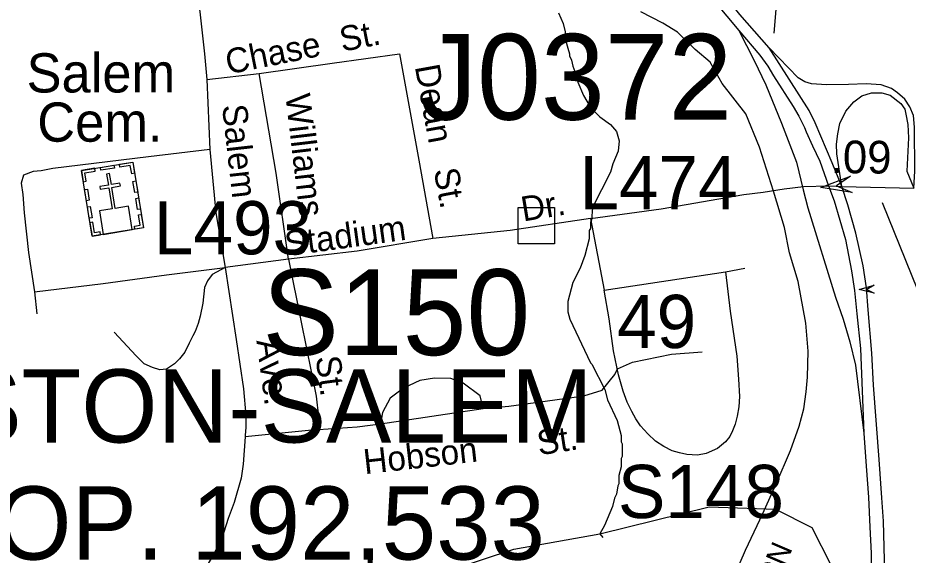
# Model space of a CAD drawing. Extents: x 1553981 to 1780076, y 812965 to 996873.
# Drawn here: x 1633663.3 to 1634089, y 847717.4 to 847974.3 of the extents above; entities that cross this region are included whole.
import ezdxf

# ---------------------------------------------------------------- set-up
doc = ezdxf.new("R2010")
doc.units = 0
for name, color, linetype in [('Exist Aviation Commercial or Municipal CELL', 7, 'Continuous'), ('Exist Aviation Field Marked Auxiliary CELL', 7, 'Continuous'), ('Exist Cultural School High CELL', 7, 'Continuous'), ('Exist Hydrographic Creek Single Shore', 7, 'Continuous'), ('Exist Hydrographic Misc Water Feature', 7, 'Continuous'), ('Exist Railroad Mainline', 7, 'Continuous'), ('Exist Railroad Mainline Label', 7, 'Continuous'), ('Exist Road Non-System Structure Non-Sys Other CELL', 7, 'Continuous'), ('Exist Road Non-System Structure Non-Sys Other Number Label', 7, 'Continuous'), ('Exist Road Non-System Type 51 Label', 7, 'Continuous'), ('Exist Road Primary Interstate Structure Cantilever Sign Number Label', 7, 'Continuous'), ('Exist Road Primary Interstate Structure Ovrhead Sign Number Label', 7, 'Continuous'), ('Exist Road Primary US Divided Attributed', 7, 'Continuous'), ('Exist Road Primary US Ramp 1 Lane  Attributed', 7, 'Continuous'), ('Exist Road Secondary Mileage Hundredths English Label', 7, 'Continuous'), ('Exist Road Secondary Structure Standard Bridge Attributed CELL', 7, 'Continuous'), ('Exist Road Secondary Structure Standard Bridge Number Label', 7, 'Continuous'), ('Exist Road Secondary Type 51 Number Label', 7, 'Continuous'), ('Exist Road Secondary Type 51 Undivided 4 Lane Attributed', 7, 'Continuous'), ('Map Preparation Border Black Inside Shape', 7, 'Continuous'), ('Map Preparation Border County Name Lower Right Label', 7, 'Continuous')]:
    doc.layers.add(name, color=color, linetype=linetype)

msp = doc.modelspace()

# ---------------------------------------------------------------- linework, layer by layer
at = {"layer": 'Exist Aviation Commercial or Municipal CELL'}
for points in [[(1633693.69, 847901.36), (1633718.25, 847905.37), (1633723.38, 847873.96), (1633698.82, 847869.94)], [(1633694.56, 847896.01), (1633695.96, 847896.24), (1633695.31, 847900.21), (1633700.31, 847901.03), (1633700.09, 847902.4), (1633693.69, 847901.36)], [(1633702.82, 847902.85), (1633709.22, 847903.89), (1633709.45, 847902.49), (1633703.05, 847901.44)], [(1633719.13, 847900.02), (1633717.73, 847899.79), (1633717.08, 847903.76), (1633712.08, 847902.95), (1633711.85, 847904.32), (1633718.26, 847905.36)], [(1633704.13, 847870.82), (1633717.97, 847873.08), (1633716.14, 847884.25), (1633709.89, 847883.23), (1633708.24, 847893.28), (1633712.31, 847893.95), (1633712.09, 847895.3), (1633708.02, 847894.64), (1633707.17, 847899.85), (1633705.74, 847899.61), (1633706.58, 847894.4), (1633702.5, 847893.74), (1633702.73, 847892.38), (1633706.81, 847893.05), (1633708.45, 847883), (1633702.31, 847881.99)], [(1633719.19, 847890.78), (1633718.32, 847896.12), (1633719.73, 847896.35), (1633720.6, 847891.01)], [(1633696.05, 847886.86), (1633695.18, 847892.21), (1633696.58, 847892.44), (1633697.46, 847887.09)], [(1633720.52, 847882.64), (1633719.65, 847887.99), (1633721.05, 847888.22), (1633721.92, 847882.87)], [(1633697.4, 847878.57), (1633696.53, 847883.92), (1633697.94, 847884.14), (1633698.81, 847878.8)], [(1633702.9, 847870.62), (1633702.67, 847872.03), (1633699.95, 847871.59), (1633699.14, 847876.58), (1633697.76, 847876.35), (1633698.81, 847869.95)], [(1633719.29, 847873.29), (1633719.06, 847874.71), (1633721.77, 847875.15), (1633720.96, 847880.14), (1633722.33, 847880.36), (1633723.38, 847873.96)]]:
    msp.add_lwpolyline(points, close=True, dxfattribs=at)
at = {"layer": 'Exist Cultural School High CELL'}
msp.add_lwpolyline([(1634072.85, 847842.71), (1634065.58, 847844.42), (1634072.73, 847846.57), (1634069.31, 847844.53)], close=True, dxfattribs=at)
at = {"layer": 'Exist Hydrographic Creek Single Shore'}
msp.add_lwpolyline([(1633841.53, 847700.95), (1633900.53, 847720.26), (1633941.52, 847727.72), (1633993.82, 847740.59), (1634025.62, 847739.48), (1634042.95, 847730.63), (1634052.01, 847712.87)], dxfattribs=at)
at = {"layer": 'Exist Hydrographic Misc Water Feature'}
for points in [[(1633921.79, 847976.7), (1633924.01, 847971.68), (1633924.97, 847967.67), (1633925.2, 847963.68), (1633927.15, 847957.16), (1633927.14, 847956.17), (1633928.12, 847954.16), (1633928.61, 847951.16), (1633930.57, 847946.15), (1633931.05, 847943.64), (1633933.75, 847937.13), (1633936.97, 847931.85), (1633941.67, 847927.07), (1633946.64, 847923.29), (1633949.62, 847920.01), (1633950.83, 847915.51), (1633950.29, 847910.52), (1633947.76, 847904.54), (1633946.73, 847900.55), (1633938.12, 847883.63), (1633937.58, 847877.64), (1633937.07, 847876.64), (1633937.06, 847873.64), (1633936.54, 847872.65), (1633936.52, 847868.65), (1633934.47, 847860.67), (1633932.17, 847854.7), (1633928.62, 847847.73), (1633926.32, 847838.76), (1633926.28, 847833.76), (1633927.25, 847830.26), (1633937.09, 847809.44), (1633937.84, 847808.69), (1633944, 847796.65), (1633945.22, 847791.64), (1633949.9, 847781.86), (1633951.85, 847774.6), (1633951.82, 847771.6), (1633952.31, 847770.6), (1633952.27, 847764.6), (1633951.77, 847763.61), (1633951.73, 847759.61), (1633950.7, 847755.62), (1633950.68, 847751.63), (1633950.18, 847750.63), (1633949.64, 847746.64)], [(1633949.64, 847746.64), (1633948.63, 847744.65), (1633947.6, 847740.66), (1633943.8, 847731.7), (1633941.52, 847727.72), (1633943, 847725.96)]]:
    msp.add_lwpolyline(points, dxfattribs=at)
at = {"layer": 'Exist Railroad Mainline'}
for points in [[(1633978.74, 847967.43), (1633971.8, 847971.78), (1633961.13, 847977.15)], [(1634006.19, 847708.12), (1634011.33, 847719.83), (1634019.6, 847737.38), (1634025.88, 847751.58), (1634032.84, 847767.5), (1634036.94, 847779.2), (1634039.19, 847787.44), (1634040.31, 847795.49), (1634040.87, 847802.61), (1634041.25, 847814.97), (1634040.03, 847828.37), (1634036.47, 847848.27), (1634032.35, 847861.94), (1634029.91, 847874.07), (1634024.58, 847891.4), (1634017.93, 847912.47), (1634011.37, 847928.49), (1634000.06, 847942.88), (1633994.32, 847953.16), (1633987.26, 847959.16), (1633978.74, 847967.43)]]:
    msp.add_lwpolyline(points, dxfattribs=at)
at = {"layer": 'Exist Road Non-System Structure Non-Sys Other CELL'}
msp.add_lwpolyline([(1633902.53, 847883.71), (1633919.9, 847883.71), (1633919.9, 847866.33), (1633902.53, 847866.33)], close=True, dxfattribs=at)
at = {"layer": 'Exist Road Primary US Divided Attributed'}
for points in [[(1633981.39, 848001.53), (1633996.66, 847981.94), (1634008.08, 847968.23)], [(1634022.6, 847959.97), (1634008.52, 847975.86), (1634001.08, 847985.45)], [(1634008.08, 847968.23), (1634018.15, 847956.5), (1634021.96, 847951.18), (1634024.61, 847946.53), (1634034, 847931.87), (1634036.74, 847927.3), (1634039.46, 847921.92), (1634040.22, 847919.83), (1634043.31, 847913.22), (1634046.77, 847905.82), (1634050.94, 847894.05)], [(1634057.31, 847893.62), (1634052.72, 847905.05), (1634044.63, 847924.18), (1634041.68, 847930.02), (1634022.6, 847959.97)], [(1634050.94, 847894.05), (1634053.66, 847886.88), (1634059.04, 847868.31), (1634061.95, 847853.37), (1634063.44, 847843.92), (1634064.47, 847832.86), (1634066.24, 847816.26), (1634067.89, 847775.8)], [(1634077.73, 847702.07), (1634077.73, 847715.07), (1634077.26, 847733.75), (1634076.42, 847744.8), (1634075.11, 847763.22), (1634072.53, 847798.73), (1634071.69, 847813.99), (1634069.95, 847834.67), (1634069.06, 847845.18), (1634067.56, 847855.76), (1634064.05, 847871.33), (1634060.12, 847885.01), (1634057.31, 847893.62)], [(1634067.89, 847775.8), (1634069.02, 847759.93), (1634070.06, 847745.24), (1634070.74, 847730.81), (1634071.36, 847718.44), (1634071.36, 847706.35), (1634071.17, 847704.2)]]:
    msp.add_lwpolyline(points, dxfattribs=at)
at = {"layer": 'Exist Road Primary US Ramp 1 Lane  Attributed'}
for points in [[(1634008.08, 847968.23), (1634015.45, 847953.99), (1634021.05, 847942.28), (1634028.43, 847923.94), (1634035.56, 847905.34), (1634038.87, 847892.09)], [(1634091.82, 847892.95), (1634092.26, 847900.98), (1634092.14, 847922.12), (1634091.63, 847927.72), (1634089.84, 847931.8), (1634087.43, 847935.49), (1634083.99, 847938.55), (1634081.06, 847940.59), (1634076.17, 847942.38), (1634068.98, 847942.74), (1634060.44, 847942.5), (1634050.01, 847942.24), (1634042.75, 847942.75), (1634039.7, 847943.77), (1634036.39, 847945.68), (1634022.6, 847959.97)], [(1634057.31, 847893.62), (1634054.97, 847909.26), (1634054.72, 847913.97), (1634055.35, 847918.94), (1634056.37, 847923.78), (1634059.3, 847929.64), (1634062.99, 847934.22), (1634066.81, 847937), (1634071.48, 847938.43), (1634074.55, 847938.43)], [(1634074.55, 847938.43), (1634076.51, 847938.43), (1634080.46, 847937.35), (1634085.49, 847933.4), (1634087.43, 847930.65), (1634087.94, 847928.23), (1634088.95, 847923.27), (1634089.21, 847917.03), (1634088.44, 847900.98), (1634091.82, 847892.95)], [(1634038.87, 847892.09), (1634041.05, 847883.57), (1634054.21, 847840.84), (1634057.9, 847830.22), (1634061.13, 847819.37), (1634063.9, 847808.28), (1634067.89, 847775.8)]]:
    msp.add_lwpolyline(points, dxfattribs=at)
at = {"layer": 'Exist Road Secondary Structure Standard Bridge Attributed CELL'}
msp.add_lwpolyline([(1634062.27, 847890.84), (1634047.21, 847893.19), (1634061.42, 847898.69), (1634054.78, 847894)], close=True, dxfattribs=at)
at = {"layer": 'Exist Road Secondary Type 51 Number Label'}
msp.add_line((1634076.67, 847886.08), (1634114.1, 847793.03), dxfattribs=at)
at = {"layer": 'Exist Road Secondary Type 51 Undivided 4 Lane Attributed'}
for points in [[(1634050.94, 847894.05), (1634054.55, 847893.81), (1634057.31, 847893.62)], [(1634057.31, 847893.62), (1634091.82, 847892.95)]]:
    msp.add_lwpolyline(points, dxfattribs=at)
at = {"layer": 'Map Preparation Border County Name Lower Right Label'}
for p, q in [((1634025.74, 847978.24), (1634024.83, 847967.04)), ((1633753.67, 847944.9), (1633778.68, 847947.72)), ((1633753.67, 847944.9), (1633755.08, 847911.43)), ((1633937.13, 847878.4), (1633943.64, 847844.21)), ((1633792.76, 847858.92), (1633762.48, 847855.05)), ((1633943.64, 847844.21), (1634001.67, 847852.91)), ((1634001.67, 847852.91), (1634010.94, 847854.59)), ((1633671.27, 847843.42), (1633672.33, 847832.85)), ((1633807, 847777.47), (1633825.62, 847778.87)), ((1633807, 847777.47), (1633771.99, 847774))]:
    msp.add_line(p, q, dxfattribs=at)
for points in [[(1633744.55, 848008.51), (1633745.98, 848003.98), (1633747.19, 847999.48), (1633748.16, 847995.48), (1633749.41, 847985.5), (1633750.48, 847975.7), (1633752.56, 847957.2), (1633753.67, 847944.9)], [(1633778.68, 847947.72), (1633813.54, 847952.65), (1633845.73, 847957.08), (1633855, 847906.26), (1633861.79, 847868.79)], [(1633792.76, 847858.92), (1633786.78, 847900.15), (1633778.68, 847947.72)], [(1633755.08, 847911.43), (1633725.85, 847907.9), (1633680.07, 847902.27), (1633674.44, 847901.21), (1633670.56, 847900.86), (1633665.99, 847899.09), (1633664.93, 847895.22), (1633665.63, 847889.93), (1633666.34, 847881.12), (1633668.45, 847862.09), (1633671.27, 847843.42)], [(1633755.08, 847911.43), (1633757.9, 847881.12), (1633762.48, 847855.05)], [(1633937.13, 847878.4), (1633970.9, 847883.08), (1634010.41, 847889.91), (1634019.75, 847890.98), (1634029.73, 847892.62), (1634039, 847893.65), (1634050.94, 847894.05)], [(1633937.13, 847878.4), (1633898.76, 847872.67), (1633861.79, 847868.79)], [(1633861.79, 847868.79), (1633825.51, 847862.8), (1633792.76, 847858.92)], [(1633671.27, 847843.42), (1633704.02, 847847.3), (1633734.31, 847851.52), (1633762.48, 847855.05)], [(1633762.48, 847855.05), (1633756.18, 847851.6), (1633753.92, 847848.62), (1633752.63, 847845.37), (1633751.82, 847837.88), (1633750.5, 847831.79), (1633749.45, 847828.27), (1633748.04, 847824.39), (1633746.98, 847822.28), (1633745.22, 847818.75), (1633743.11, 847814.52), (1633740.64, 847811.35), (1633738.18, 847808.89), (1633734.31, 847806.42), (1633731.14, 847806.07), (1633727.61, 847807.13), (1633723.74, 847808.89), (1633719.87, 847812.76), (1633709.3, 847824.04)], [(1633762.48, 847855.05), (1633767.76, 847820.52), (1633771.28, 847796.91), (1633772.34, 847784.22), (1633772.34, 847778.58), (1633771.99, 847774.71), (1633771.99, 847774)], [(1633792.76, 847858.92), (1633798.72, 847828.83), (1633805.89, 847793.48), (1633807, 847783.54), (1633807, 847777.47)], [(1634001.67, 847852.91), (1634003.99, 847834.15), (1634007.06, 847812.63), (1634007.94, 847801.63), (1634008.37, 847793.36), (1634008.07, 847788.37), (1634007.28, 847783.88), (1634006.25, 847780.12), (1634004.96, 847776.9), (1634003.7, 847774.15), (1634001.67, 847771.66), (1633997.91, 847768.46), (1633992.38, 847766), (1633988.36, 847765.3), (1633983.14, 847765.59), (1633979.63, 847766.38), (1633976.15, 847767.4), (1633972.16, 847769.44), (1633968.19, 847771.97), (1633964.48, 847775.52), (1633961.03, 847779.29), (1633958.8, 847782.56), (1633956.84, 847786.08), (1633954.63, 847790.6), (1633952.69, 847795.87)], [(1633952.69, 847795.87), (1633950.5, 847803.64), (1633948.1, 847815.15), (1633946.01, 847830.42), (1633943.64, 847844.21)], [(1633950.06, 847806.47), (1633957.2, 847809.79), (1633975.86, 847813.62), (1633990.53, 847814.74)], [(1633898.11, 847788.75), (1633933.95, 847793.7), (1633942.72, 847796.41), (1633948.78, 847803.75), (1633950.06, 847806.47)], [(1633885.83, 847787.63), (1633884.4, 847793.7), (1633876.26, 847799.61), (1633870.36, 847801.84), (1633862.55, 847802), (1633855.53, 847800.88), (1633847.71, 847797.37), (1633841.33, 847792.58), (1633837.67, 847785.72), (1633836.71, 847780.29)], [(1633836.71, 847780.29), (1633885.83, 847787.63)], [(1633885.83, 847787.63), (1633898.11, 847788.75)], [(1633825.62, 847778.87), (1633836.71, 847780.29)], [(1633771.99, 847774), (1633771.12, 847760.9), (1633770.01, 847754.27), (1633766.7, 847742.67), (1633763.94, 847734.94), (1633760.63, 847724.99), (1633756.21, 847716.71), (1633745.12, 847698.16), (1633736.57, 847684.01)]]:
    msp.add_lwpolyline(points, dxfattribs=at)

# ---------------------------------------------------------------- texts
at = {"layer": 'Exist Aviation Field Marked Auxiliary CELL'}
for s, p in [('Salem', (1633667.47, 847938.64)), ('Cem.', (1633672.59, 847915.12))]:
    msp.add_text(s, height=18.75, dxfattribs=at).set_placement(p)
at = {"layer": 'Exist Railroad Mainline Label'}
msp.add_text('Norfolk', height=10.253, rotation=246.808, dxfattribs=at).set_placement((1634024.51, 847724.76))
at = {"layer": 'Exist Road Non-System Structure Non-Sys Other Number Label'}
msp.add_text('J0372', height=41.01, dxfattribs=at).set_placement((1633855.5, 847925.63))
at = {"layer": 'Exist Road Non-System Type 51 Label'}
for s, rotation, p in [('St.', 10.8728, (1633818.38, 847958.09)), ('Chase', 11.2861, (1633763.87, 847947.26)), ('Dean', 280.3416, (1633853.09, 847951.05)), ('Williams', 276.7642, (1633791.2, 847937.35)), ('Salem', 276.3993, (1633760.92, 847932.4)), ('St.', 280.4054, (1633862.12, 847901.57)), ('Dr.', 9.3595, (1633904.95, 847876.93)), ('Stadium', 7.8428, (1633791.76, 847860.35)), ('Ave.', 277.4883, (1633777.35, 847820.01)), ('St.', 277.4896, (1633805.67, 847812.11)), ('St.', 8.7473, (1633912.51, 847765.17)), ('Hobson', 6.4158, (1633829.2, 847756.15))]:
    msp.add_text(s, height=11.875, rotation=rotation, dxfattribs=at).set_placement(p)
at = {"layer": 'Exist Road Primary Interstate Structure Cantilever Sign Number Label'}
for s, p in [('L474', (1633931.84, 847882.85)), ('L493', (1633728.38, 847861.26))]:
    msp.add_text(s, height=25.426, dxfattribs=at).set_placement(p)
at = {"layer": 'Exist Road Primary Interstate Structure Ovrhead Sign Number Label'}
for s, height, p in [('S150', 41.01, (1633780.24, 847813.11)), ('S148', 25.426, (1633950.24, 847735.2))]:
    msp.add_text(s, height=height, dxfattribs=at).set_placement(p)
at = {"layer": 'Exist Road Secondary Mileage Hundredths English Label'}
msp.add_text('.09', height=15.625, rotation=359.4698, dxfattribs=at).set_placement((1634051.96, 847900.11))
at = {"layer": 'Exist Road Secondary Structure Standard Bridge Number Label'}
msp.add_text('49', height=25.426, dxfattribs=at).set_placement((1633949.84, 847816.47))
at = {"layer": 'Map Preparation Border Black Inside Shape'}
for s, p in [('WINSTON-SALEM', (1633542.89, 847771.31)), ('POP. 192,533', (1633621.35, 847715.34))]:
    msp.add_text(s, height=35, dxfattribs=at).set_placement(p)

doc.saveas('drawing.dxf')
